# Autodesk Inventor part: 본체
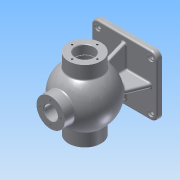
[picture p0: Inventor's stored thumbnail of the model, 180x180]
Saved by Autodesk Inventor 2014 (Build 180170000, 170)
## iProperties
Created: 2017-01
Part Number: 본체
Material: Aluminum 6061
Document SubType Name: Modeling
Designer: ksu
Density: 2.71 g/cm^3
Appearance: Aluminum - Flat
Author: ksu
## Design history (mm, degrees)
sketch "Sketch1"
  geometry: L1 (-62.5, -57.5)-(62.5, -57.5); L2 (62.5, -57.5)-(62.5, 57.5); L3 (62.5, 57.5)-(-62.5, 57.5); L4 (-62.5, 57.5)-(-62.5, -57.5); L5 (-62.5, -57.5)-(62.5, 57.5); L6 (62.5, -57.5)-(-62.5, 57.5); 1 further point
  constraints: 12 end point, 2 midpoint, 2 parallel, 1 horizontal, 1 perpendicular
  dimensions: "d0" = 125 distance of L3.end L2.end; "d1" = 115 distance of L2.end L1.end
extrude "Extrusion1" new body sketch "Sketch1" distance "d2" = 10; taper "d3" = 0 deg
sketch "Sketch2"
  geometry: L1 (-57.5, 0)-(57.5, 0) reference; L2 (-68, 85)-(106.185, 85); L3 (-68, 116)-(-68, 102.5); L4 (68, 116)-(68, 102.5); L5 (-68, 116)-(-42.988, 116); L6 (42.988, 116)-(68, 116); L7 (-68, 102.5)-(-39.278, 102.5); L8 (39.278, 102.5)-(68, 102.5); A1 r 53 centre (0, 85) between (42.988, 116) and (-42.988, 116); A2 r 43 centre (0, 85) between (39.278, 102.5) and (-39.278, 102.5); 1 further point
  constraints: 14 end point, 6 parallel, 4 point on circle, 2 centre point, 1 coincident
  dimensions: "d4" = 106 diameter of A1; "d5" = 86 diameter of A2; "d6" = 85 distance from line of L1 A2.centre; "d9" = 136 distance of L3.start L4.start; "d10" = 68 horizontal distance of point (0, 0) L4.start; "d11" = 136 distance of L3.end L4.end; "d12" = 68 horizontal distance of point (0, 0) L4.end
revolve "Revolution1" sketch "Sketch2" stored, may be unused: angle "d13" = 90 deg
workplane "Work Plane1"
sketch "Sketch3"
  geometry: C1 r 27 at (0, 0); 1 further point
  constraints: 1 centre point, 1 coincident
  dimensions: "d15" = 54 diameter of C1
extrude "Extrusion2" join sketch "Sketch3" distance "d16" = 30; taper "d17" = 0 deg
sketch "Sketch4"
  geometry: C1 r 27 at (0, 0) reference; C2 r 13 at (0, 0)
  constraints: 1 centre point, 1 coincident
  dimensions: "d18" = 26 diameter of C2
extrude "Extrusion3" cut sketch "Sketch4" distance "d19" = 30; taper "d20" = 0 deg
sketch "Sketch5"
  geometry: L1 (62.5, 10)-(-62.5, 10) reference; L2 (-35.008, 53.295)-(-52.5, 10); L3 (35.008, 53.295)-(52.5, 10); L4 (-52.5, 10)-(52.5, 10); L5 (-62.5, 0)-(-62.5, 10) reference; L6 (62.5, 0)-(62.5, 10) reference; A1 r 47.231 centre (0, 85) between (-35.008, 53.295) and (35.008, 53.295); 3 further points
  constraints: 6 end point, 4 point on line, 2 point on circle, 1 centre point, 1 collinear
  dimensions: "d21" = 10 distance of L1.end L2.end; "d22" = 10 distance of L1.start L3.end; "d23" = 22 deg angle of L5 L2; "d24" = 22 deg angle of L6 L3
extrude "Extrusion4" join sketch "Sketch5" stored distance "d25" = 8; taper "d26" = 0 deg
sketch "Sketch6"
  geometry: L1 (57.5, 10)-(-57.5, 10) reference; L2 (-30.87, 51.162)-(-47.5, 10); L3 (30.87, 51.162)-(47.5, 10); L4 (-47.5, 10)-(47.5, 10); L5 (-57.5, 0)-(-57.5, 10) reference; L6 (57.5, 0)-(57.5, 10) reference; A1 r 45.804 centre (0, 85) between (-30.87, 51.162) and (30.87, 51.162); 1 further point
  constraints: 6 end point, 2 point on circle, 2 point on line, 1 centre point, 1 collinear
  dimensions: "d27" = 10 distance of L1.end L2.end; "d28" = 10 distance of L1.start L3.end; "d29" = 22 deg angle of L5 L2; "d30" = 22 deg angle of L6 L3
extrude "Extrusion5" join sketch "Sketch6" stored distance "d31" = 8; taper "d32" = 0 deg
fillet "Fillet1" dims "d33" = 12
sketch "Sketch7"
  geometry: A1 r 12 centre (-50.5, 45.5) between (-50.5, 57.5) and (-62.5, 45.5) reference; A2 r 12 centre (-50.5, -45.5) between (-62.5, -45.5) and (-50.5, -57.5) reference; A3 r 12 centre (50.5, -45.5) between (50.5, -57.5) and (62.5, -45.5) reference; A4 r 12 centre (50.5, 45.5) between (62.5, 45.5) and (50.5, 57.5) reference; 5 further points
  constraints: 4 coincident
hole "Hole1" sketch "Sketch7" at (-50.5, 45.5), (50.5, 45.5), (50.5, -45.5), (-50.5, -45.5) diameter "d34" = 8; stored, may be unused: countersink angle "d38" = 90 deg, drill point angle "d40" = 118 deg; dims "d35" = 6, "d36" = 12, "d37" = 3, "d39" = 10
sketch "Sketch8" dims "d41" = 45
  geometry: C1 r 31 at (0, 0) reference; 3 further points
  constraints: 1 coincident, 1 vertical alignment, 2 other
hole "Hole2" sketch "Sketch8" at (0, 22.5) diameter "d42" = 3.459; stored, may be unused: countersink angle "d46" = 90 deg, drill point angle "d48" = 118 deg; dims "d43" = 12, "d44" = 12, "d45" = 3, "d47" = 15
workaxis "Work Axis1"
pattern_circular "Circular Pattern1" dims angle "d50" = 360 deg
sketch "Sketch9" dims "d52" = 48
  geometry: C1 r 17.5 at (0, 0) reference; 3 further points
  constraints: 1 coincident, 1 vertical alignment, 2 other
hole "Hole3" sketch "Sketch9" at (0, 24) diameter "d53" = 3.459; stored, may be unused: countersink angle "d57" = 90 deg, drill point angle "d59" = 118 deg; dims "d54" = 16, "d55" = 12, "d56" = 3, "d58" = 19
pattern_circular "Circular Pattern2" dims angle "d61" = 360 deg
workplane "Work Plane2"
sketch "Sketch10"
  geometry: L1 (142.729, 66.239)-(142.729, 24.761); L2 (142.729, 24.761)-(137.271, 24.761); L3 (137.271, 24.761)-(137.271, 66.239); L4 (137.271, 66.239)-(142.729, 66.239); L5 (140, 66.239)-(140, 24.761); L6 (142.729, 45.5)-(137.271, 45.5); L7 (150, 72.5)-(130.607, 72.5) reference; 2 further points
  constraints: 5 midpoint, 4 end point, 2 other
  dimensions: "d64" = 27 distance from line of L7.start L6; "d97" = 10 horizontal distance of L7.start point (140, 45.5)
emboss "Emboss1" sketch "Sketch10" dims "d0" = 125, "d1" = 115, "d66" = 0.5, "d67" = 0
sketch "Sketch11"
  geometry: L1 (-27.094, 118.39)-(-27.094, 85); L2 (-27.094, 85)-(31.416, 85); L3 (31.416, 85)-(31.543, 114.224); L4 (-95.2, 85)-(95.2, 85) reference; A1 r 43 centre (0, 85) between (-24.98, 120) and (24.98, 120) reference; A2 r 43 centre (0, 85) between (31.543, 114.224) and (-27.094, 118.39); 1 further point
  constraints: 6 end point, 4 point on circle, 1 centre point, 1 coincident, 1 concentric, 1 perpendicular, 1 vertical
revolve "Revolution2" sketch "Sketch11" stored, may be unused: angle "d68" = 90 deg
chamfer "Chamfer1" distance "d69" = 1; stored, may be unused: second distance "d70" = 2, angle "d71" = 45 deg
sketch "Sketch12"
  geometry: L1 (50.25, 103.5)-(52, 103.5); L2 (52, 103.5)-(52, 85); L3 (52, 85)-(50.25, 85); L4 (50.25, 85)-(50.25, 103.5); L5 (45.5, 0)-(-45.5, 0) reference; L6 (68, 66.5)-(68, 103.5) reference; L7 (-95.2, 85)-(95.2, 85) reference; 1 further point
  constraints: 8 end point, 2 parallel, 1 horizontal, 1 perpendicular
  dimensions: "d72" = 85 distance between parallel lines of L5 L3; "d73" = 1.75 distance of L1.start L1.end; "d74" = 16 distance between parallel lines of L6 L2; "d76" = 18.5 distance between parallel lines of L3 L1
revolve "Revolution3" sketch "Sketch12" stored, may be unused: angle "d75" = 90 deg
sketch "Sketch13" dims "d77" = 40
  geometry: C1 r 27 at (0, 0) reference; 2 further points
  constraints: 1 coincident, 1 vertical alignment, 2 other
hole "Hole4" sketch "Sketch13" at (0, 20) diameter "d78" = 3.459; stored, may be unused: countersink angle "d82" = 90 deg, drill point angle "d84" = 118 deg; dims "d79" = 9, "d80" = 12, "d81" = 3, "d83" = 11
workaxis "Work Axis2"
pattern_circular "Circular Pattern3" dims angle "d86" = 360 deg
fillet "Fillet2" dims "d88" = 3
fillet "Fillet3" dims "d89" = 3
fillet "Fillet4" dims "d90" = 3
fillet "Fillet5" dims "d91" = 3
fillet "Fillet6" dims "d92" = 3
fillet "Fillet7" dims "d93" = 3
chamfer "Chamfer2" distance "d94" = 1; stored, may be unused: second distance "d95" = 2, angle "d96" = 45 deg
body "Solid1"
other parameters: "d7" = 62, "d8" = 35
